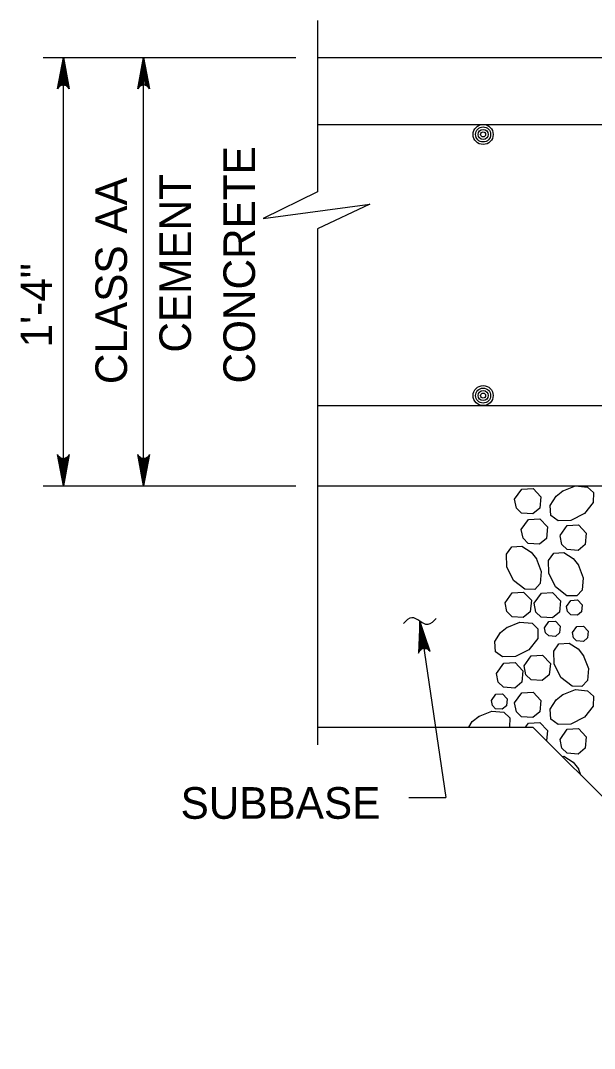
# Model space of a CAD drawing. Extents: x 638079 to 640019, y 297691 to 298879.
# Drawn here: x 639553.1 to 639607.5, y 298707.6 to 298805.1 of the extents above; entities that cross this region are included whole.
import ezdxf

# ---------------------------------------------------------------- set-up
doc = ezdxf.new("R2010")
doc.units = 0
doc.layers.add('1', color=7, linetype='Continuous')

msp = doc.modelspace()

# ---------------------------------------------------------------- linework, layer by layer
at = {"layer": '1'}
for p, q in [((639581.264, 298805.075), (639581.264, 298788.828)), ((639555.226, 298801.575), (639579.206, 298801.575)), ((639557.131, 298760.936), (639557.131, 298801.575)), ((639564.751, 298760.936), (639564.751, 298801.575)), ((639581.264, 298801.575), (639723.606, 298801.575)), ((639581.264, 298795.225), (639630.899, 298795.225)), ((639581.264, 298785.309), (639581.264, 298736.394)), ((639581.264, 298768.557), (639630.899, 298768.557)), ((639555.226, 298760.936), (639579.206, 298760.936)), ((639581.264, 298760.936), (639723.606, 298760.936)), ((639590.962, 298748.114), (639593.437, 298731.388)), ((639581.264, 298738.076), (639601.686, 298738.076)), ((639632.166, 298707.596), (639601.686, 298738.076)), ((639589.92, 298731.388), (639593.437, 298731.388))]:
    msp.add_line(p, q, dxfattribs=at)
for points in [[(639557.131, 298801.575), (639557.69, 298798.592), (639557.611, 298798.707), (639557.531, 298798.822), (639557.431, 298798.881), (639557.331, 298798.941), (639557.231, 298798.958), (639557.131, 298798.975), (639557.031, 298798.958), (639556.931, 298798.941), (639556.831, 298798.881), (639556.731, 298798.822), (639556.651, 298798.707), (639556.572, 298798.592), (639557.131, 298801.575), (639556.651, 298798.707), (639556.731, 298798.822), (639557.131, 298801.575), (639556.831, 298798.881), (639556.931, 298798.941), (639557.131, 298801.575), (639557.031, 298798.958), (639557.131, 298798.975), (639557.131, 298801.575), (639557.231, 298798.958), (639557.331, 298798.941), (639557.131, 298801.575), (639557.431, 298798.881), (639557.531, 298798.822), (639557.131, 298801.575), (639557.611, 298798.707)], [(639564.751, 298801.575), (639565.31, 298798.592), (639565.231, 298798.707), (639565.151, 298798.822), (639565.051, 298798.881), (639564.951, 298798.941), (639564.851, 298798.958), (639564.751, 298798.975), (639564.651, 298798.958), (639564.551, 298798.941), (639564.451, 298798.881), (639564.351, 298798.822), (639564.271, 298798.707), (639564.192, 298798.592), (639564.751, 298801.575), (639564.271, 298798.707), (639564.351, 298798.822), (639564.751, 298801.575), (639564.451, 298798.881), (639564.551, 298798.941), (639564.751, 298801.575), (639564.651, 298798.958), (639564.751, 298798.975), (639564.751, 298801.575), (639564.851, 298798.958), (639564.951, 298798.941), (639564.751, 298801.575), (639565.051, 298798.881), (639565.151, 298798.822), (639564.751, 298801.575), (639565.231, 298798.707)], [(639581.264, 298788.828), (639576.079, 298786.29), (639586.228, 298787.67), (639581.264, 298785.309)], [(639557.131, 298760.936), (639556.572, 298763.919), (639556.651, 298763.804), (639556.731, 298763.689), (639556.831, 298763.63), (639556.931, 298763.57), (639557.031, 298763.553), (639557.131, 298763.536), (639557.231, 298763.553), (639557.331, 298763.57), (639557.431, 298763.63), (639557.531, 298763.689), (639557.611, 298763.804), (639557.69, 298763.919), (639557.131, 298760.936), (639557.611, 298763.804), (639557.531, 298763.689), (639557.131, 298760.936), (639557.431, 298763.63), (639557.331, 298763.57), (639557.131, 298760.936), (639557.231, 298763.553), (639557.131, 298763.536), (639557.131, 298760.936), (639557.031, 298763.553), (639556.931, 298763.57), (639557.131, 298760.936), (639556.831, 298763.63), (639556.731, 298763.689), (639557.131, 298760.936), (639556.651, 298763.804)], [(639564.751, 298760.936), (639564.192, 298763.919), (639564.271, 298763.804), (639564.351, 298763.689), (639564.451, 298763.63), (639564.551, 298763.57), (639564.651, 298763.553), (639564.751, 298763.536), (639564.851, 298763.553), (639564.951, 298763.57), (639565.051, 298763.63), (639565.151, 298763.689), (639565.231, 298763.804), (639565.31, 298763.919), (639564.751, 298760.936), (639565.231, 298763.804), (639565.151, 298763.689), (639564.751, 298760.936), (639565.051, 298763.63), (639564.951, 298763.57), (639564.751, 298760.936), (639564.851, 298763.553), (639564.751, 298763.536), (639564.751, 298760.936), (639564.651, 298763.553), (639564.551, 298763.57), (639564.751, 298760.936), (639564.451, 298763.63), (639564.351, 298763.689), (639564.751, 298760.936), (639564.271, 298763.804)], [(639599.956, 298759.673), (639600.628, 298760.63), (639601.701, 298760.691), (639602.447, 298759.917), (639602.339, 298758.833), (639601.676, 298758.282), (639600.617, 298758.358), (639600.118, 298758.842), (639599.956, 298759.673)], [(639605.725, 298760.936), (639606.88, 298760.837), (639607.429, 298760.315), (639607.412, 298759.377), (639606.578, 298758.312), (639605.29, 298757.668), (639604.076, 298757.647), (639603.393, 298758.132), (639603.328, 298759.099), (639603.883, 298759.964), (639604.518, 298760.47)], [(639604.467, 298760.438), (639605.725, 298760.936)], [(639600.588, 298756.81), (639601.26, 298757.767), (639602.334, 298757.828), (639603.08, 298757.054), (639602.972, 298755.97), (639602.309, 298755.419), (639601.249, 298755.495), (639600.751, 298755.979), (639600.589, 298756.81)], [(639604.264, 298756.225), (639604.936, 298757.181), (639606.009, 298757.242), (639606.755, 298756.469), (639606.647, 298755.385), (639605.984, 298754.833), (639604.925, 298754.91), (639604.426, 298755.393), (639604.264, 298756.224)], [(639601.987, 298754.086), (639602.486, 298752.828), (639602.386, 298751.673), (639601.864, 298751.124), (639600.926, 298751.141), (639599.861, 298751.975), (639599.217, 298753.263), (639599.196, 298754.476), (639599.681, 298755.16), (639600.648, 298755.224), (639601.513, 298754.67), (639602.019, 298754.035)], [(639605.973, 298753.476), (639606.471, 298752.218), (639606.372, 298751.063), (639605.85, 298750.514), (639604.912, 298750.531), (639603.847, 298751.365), (639603.203, 298752.653), (639603.182, 298753.866), (639603.667, 298754.55), (639604.634, 298754.614), (639605.499, 298754.06), (639606.005, 298753.425)], [(639599.053, 298749.854), (639599.725, 298750.811), (639600.798, 298750.872), (639601.544, 298750.098), (639601.436, 298749.014), (639600.773, 298748.463), (639599.714, 298748.539), (639599.215, 298749.023), (639599.053, 298749.854)], [(639601.818, 298749.813), (639602.49, 298750.77), (639603.564, 298750.831), (639604.31, 298750.057), (639604.202, 298748.973), (639603.539, 298748.422), (639602.479, 298748.499), (639601.981, 298748.982), (639601.819, 298749.813)], [(639604.877, 298749.518), (639605.28, 298750.092), (639605.925, 298750.129), (639606.372, 298749.664), (639606.307, 298749.014), (639605.91, 298748.683), (639605.274, 298748.729), (639604.974, 298749.019), (639604.877, 298749.518)], [(639590.962, 298748.114), (639590.845, 298745.082), (639590.907, 298745.207), (639590.969, 298745.332), (639591.059, 298745.406), (639591.15, 298745.479), (639591.246, 298745.51), (639591.342, 298745.542), (639591.444, 298745.54), (639591.545, 298745.537), (639591.653, 298745.493), (639591.761, 298745.449), (639591.856, 298745.347), (639591.952, 298745.245), (639590.962, 298748.114), (639591.856, 298745.347), (639591.761, 298745.449), (639590.962, 298748.114), (639591.653, 298745.493), (639591.545, 298745.537), (639590.962, 298748.114), (639591.444, 298745.54), (639591.342, 298745.542), (639590.962, 298748.114), (639591.246, 298745.51), (639591.15, 298745.479), (639590.962, 298748.114), (639591.059, 298745.406), (639590.969, 298745.332), (639590.962, 298748.114), (639590.907, 298745.207)], [(639599.204, 298747.52), (639600.462, 298748.019), (639601.617, 298747.919), (639602.167, 298747.397), (639602.149, 298746.459), (639601.316, 298745.394), (639600.028, 298744.75), (639598.814, 298744.729), (639598.131, 298745.214), (639598.066, 298746.181), (639598.62, 298747.046), (639599.255, 298747.552)], [(639602.796, 298747.5), (639603.2, 298748.074), (639603.844, 298748.111), (639604.291, 298747.647), (639604.227, 298746.996), (639603.829, 298746.665), (639603.193, 298746.712), (639602.894, 298747.002), (639602.797, 298747.5)], [(639605.444, 298747.028), (639605.848, 298747.601), (639606.492, 298747.638), (639606.94, 298747.174), (639606.875, 298746.524), (639606.477, 298746.193), (639605.841, 298746.239), (639605.542, 298746.529), (639605.445, 298747.027)], [(639606.46, 298744.894), (639606.959, 298743.637), (639606.859, 298742.481), (639606.337, 298741.932), (639605.4, 298741.95), (639604.334, 298742.783), (639603.691, 298744.071), (639603.669, 298745.285), (639604.155, 298745.968), (639605.122, 298746.033), (639605.986, 298745.479), (639606.493, 298744.844)], [(639600.852, 298743.87), (639601.524, 298744.826), (639602.597, 298744.888), (639603.344, 298744.114), (639603.236, 298743.03), (639602.572, 298742.478), (639601.513, 298742.555), (639601.014, 298743.039), (639600.852, 298743.87)], [(639598.244, 298743.169), (639598.917, 298744.125), (639599.99, 298744.186), (639600.736, 298743.413), (639600.628, 298742.328), (639599.965, 298741.777), (639598.905, 298741.854), (639598.407, 298742.337), (639598.245, 298743.168)], [(639597.752, 298740.607), (639598.156, 298741.18), (639598.8, 298741.217), (639599.248, 298740.753), (639599.183, 298740.103), (639598.785, 298739.772), (639598.149, 298739.818), (639597.85, 298740.108), (639597.753, 298740.606)], [(639599.956, 298740.359), (639600.628, 298741.315), (639601.701, 298741.376), (639602.447, 298740.603), (639602.339, 298739.519), (639601.676, 298738.967), (639600.617, 298739.044), (639600.118, 298739.527), (639599.956, 298740.359)], [(639604.467, 298741.123), (639605.725, 298741.622), (639606.88, 298741.522), (639607.429, 298741), (639607.412, 298740.063), (639606.578, 298738.997), (639605.29, 298738.353), (639604.076, 298738.332), (639603.393, 298738.818), (639603.328, 298739.784), (639603.883, 298740.649), (639604.518, 298741.156)], [(639595.603, 298738.076), (639595.939, 298738.6), (639596.574, 298739.106)], [(639596.523, 298739.074), (639597.78, 298739.573), (639598.936, 298739.473), (639599.485, 298738.951), (639599.469, 298738.076)], [(639600.996, 298738.076), (639601.26, 298738.452), (639602.334, 298738.513), (639603.08, 298737.74), (639602.984, 298736.778)], [(639604.264, 298736.91), (639604.936, 298737.866), (639606.009, 298737.928), (639606.755, 298737.154), (639606.647, 298736.07), (639605.984, 298735.518), (639604.925, 298735.595), (639604.426, 298736.079), (639604.264, 298736.91)], [(639604.473, 298735.289), (639604.634, 298735.3), (639605.499, 298734.746), (639606.005, 298734.111)], [(639605.973, 298734.161), (639606.217, 298733.545)]]:
    msp.add_lwpolyline(points, dxfattribs=at)
for centre, radius in [((639596.966, 298794.275), 0.952), ((639596.966, 298794.275), 0.714), ((639596.966, 298794.275), 0.476), ((639596.966, 298794.275), 0.238), ((639596.966, 298769.507), 0.952), ((639596.966, 298769.507), 0.714), ((639596.966, 298769.507), 0.476), ((639596.966, 298769.507), 0.238)]:
    msp.add_circle(centre, radius, dxfattribs=at)
msp.add_spline([(639592.5, 298748.375), (639591.713, 298747.791), (639590.203, 298748.441), (639589.421, 298747.907)], degree=3, dxfattribs=at)

# ---------------------------------------------------------------- texts
for s, p in [('CONCRETE', (639575.32, 298770.655)), ('CLASS AA', (639563.176, 298770.596)), ('CEMENT', (639569.248, 298773.584)), ('1\'-4"', (639556.07, 298774.073))]:
    msp.add_text(s, height=3, rotation=90, dxfattribs=at).set_placement(p)
msp.add_text('SUBBASE', height=3, dxfattribs=at).set_placement((639568.26, 298729.375))

doc.saveas('drawing.dxf')
